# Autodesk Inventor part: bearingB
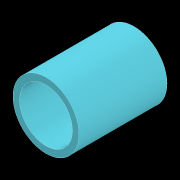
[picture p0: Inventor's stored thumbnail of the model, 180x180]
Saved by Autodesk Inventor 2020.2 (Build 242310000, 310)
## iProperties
Manager: PART
Category: 10
Company: 17
Created: 2020-10
Part Number: bearingB
Material: Generic
Document SubType Name: Modeling
Designer: Apardo
Density: 1 g/cm^3
Appearance: Cadet Blue
Project: PLATE ROLLING MACHINE
Cost Center: 1
Description: BEARING B
Engineer: STEEL C45
Vendor: 10
Stock Number: 1.13
Engr Approved By: D. JAEGER
Author: Apardo
Revision Number: 1.0
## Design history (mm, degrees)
sketch "Sketch1"
  geometry: C1 r 6.01 at (0, 0); C2 r 7.5 at (0, 0); 1 further point
  constraints: 2 centre point, 2 coincident
  dimensions: "d0" = 15 diameter of C2; "d1" = 12.02 diameter of C1
extrude "Extrusion1" new body sketch "Sketch1" stored distance "d2" = 20; taper "d3" = 0 deg
body "Solid1"
